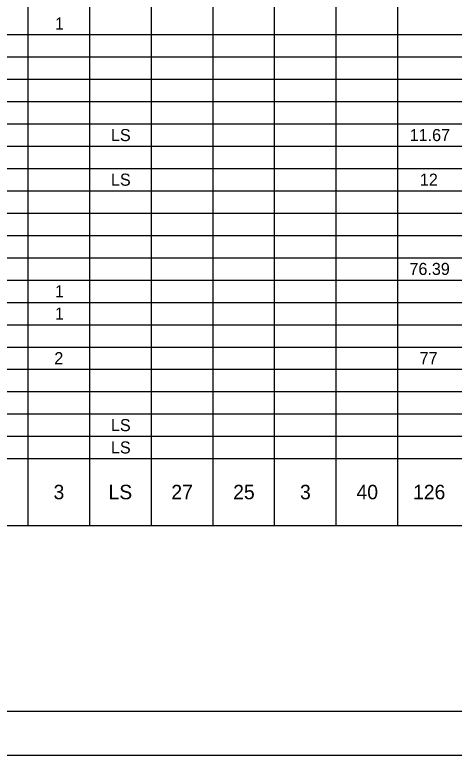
# Model space of a CAD drawing. Extents: x 0 to 34, y 0 to 22.
# Drawn here: x 24.1 to 29.12, y 0 to 8.46 of the extents above; entities that cross this region are included whole.
import ezdxf

# ---------------------------------------------------------------- set-up
doc = ezdxf.new("R2010")
doc.units = 0
for name, color, linetype in [('SH_Border', 7, 'Continuous'), ('SH_Cut_Line', 7, 'Continuous'), ('SH_Text', 7, 'Continuous')]:
    doc.layers.add(name, color=color, linetype=linetype)

msp = doc.modelspace()

# ---------------------------------------------------------------- linework, layer by layer
at = {"layer": 'SH_Border'}
msp.add_lwpolyline([(1.5, 21.5), (33.5, 21.5), (33.5, 0.5), (1.5, 0.5)], close=True, dxfattribs=at)
at = {"layer": 'SH_Cut_Line'}
msp.add_lwpolyline([(0, 0), (34, 0), (34, 22), (0, 22)], close=True, dxfattribs=at)
at = {"layer": 'SH_Text'}
for p, q in [((24.95, 21), (24.95, 2.625)), ((25.655, 21), (25.655, 2.625)), ((26.36, 21), (26.36, 2.625)), ((27.065, 21), (27.065, 2.625)), ((24.245, 20.745), (24.245, 2.625)), ((27.77, 20.745), (27.77, 2.625)), ((28.475, 20.745), (28.475, 2.625)), ((14.42, 8.235), (31.295, 8.235)), ((14.42, 7.98), (31.295, 7.98)), ((14.42, 7.725), (31.295, 7.725)), ((14.42, 7.47), (31.295, 7.47)), ((14.42, 7.215), (31.295, 7.215)), ((14.42, 6.96), (31.295, 6.96)), ((14.42, 6.705), (31.295, 6.705)), ((14.42, 6.45), (31.295, 6.45)), ((14.42, 6.195), (31.295, 6.195)), ((14.42, 5.94), (31.295, 5.94)), ((14.42, 5.685), (31.295, 5.685)), ((14.42, 5.43), (31.295, 5.43)), ((14.42, 5.175), (31.295, 5.175)), ((14.42, 4.92), (31.295, 4.92)), ((14.42, 4.665), (31.295, 4.665)), ((14.42, 4.41), (31.295, 4.41)), ((14.42, 4.155), (31.295, 4.155)), ((14.42, 3.9), (31.295, 3.9)), ((14.42, 3.645), (31.295, 3.645)), ((14.42, 3.39), (31.295, 3.39)), ((14.42, 2.625), (31.295, 2.625))]:
    msp.add_line(p, q, dxfattribs=at)

# ---------------------------------------------------------------- texts
for s, height, p in [('1', 0.138, (24.5559, 8.2935)), ('LS', 0.138, (25.196, 7.0185)), ('11.67', 0.138, (28.6135, 7.0185)), ('LS', 0.138, (25.196, 6.5085)), ('12', 0.138, (28.7305, 6.5085)), ('76.39', 0.138, (28.6109, 5.4885)), ('1', 0.138, (24.5559, 5.2335)), ('1', 0.138, (24.5559, 4.9785)), ('2', 0.138, (24.5487, 4.4685)), ('77', 0.138, (28.7276, 4.4685)), ('LS', 0.138, (25.196, 3.7035)), ('LS', 0.138, (25.196, 3.4485)), ('3', 0.1656, (24.5392, 2.9247)), ('LS', 0.1656, (25.1685, 2.9247)), ('27', 0.1656, (25.8869, 2.9247)), ('25', 0.1656, (26.5945, 2.9247)), ('3', 0.1656, (27.3592, 2.9247)), ('40', 0.1656, (28.0052, 2.9247)), ('126', 0.1656, (28.6518, 2.9247))]:
    msp.add_text(s, height=height, dxfattribs=at).set_placement(p)

doc.saveas('drawing.dxf')
